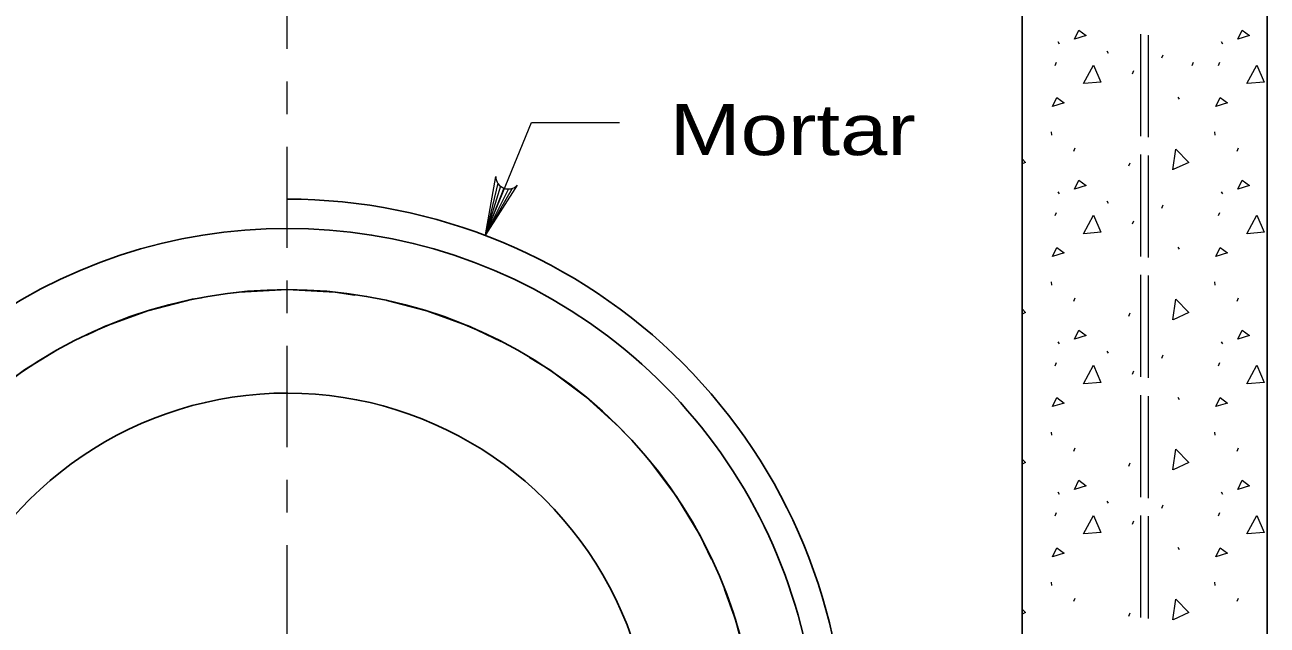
# Model space of a CAD drawing. Extents: x 1083.1 to 1117.1, y 719.4 to 763.4.
# Drawn here: x 1093.643 to 1097.446, y 731.113 to 732.95 of the extents above; entities that cross this region are included whole.
import ezdxf

# ---------------------------------------------------------------- set-up
doc = ezdxf.new("R2010")
doc.units = 0
doc.header["$LTSCALE"] = 0.062
doc.linetypes.add('DOT_DASHED', pattern=[7.7, 5, -1.2, 0.3, -1.2])
doc.linetypes.add('LONG_DASHED', pattern=[7.5, 6, -1.5])
doc.layers.add('1', color=7, linetype='Continuous', lineweight=13)

msp = doc.modelspace()

# ---------------------------------------------------------------- linework, layer by layer
at = {"layer": '1', "lineweight": 25}
msp.add_line((1096.69608, 730.80725), (1096.69608, 733.88517), dxfattribs=at)
at = {"layer": '1', "linetype": 'DOT_DASHED'}
msp.add_line((1094.44633, 731.04717), (1094.44633, 733.19283), dxfattribs=at)
at = {"layer": '1'}
for p, q in [((1096.80533, 732.89867), (1096.80983, 732.892)), ((1097.30533, 732.89867), (1097.30983, 732.892)), ((1096.95492, 732.8705), (1096.95933, 732.86383)), ((1097.12383, 732.84883), (1097.12825, 732.85875)), ((1096.797, 732.82558), (1096.80142, 732.83558)), ((1097.21667, 732.8255), (1097.22108, 732.8355)), ((1097.297, 732.82558), (1097.30142, 732.83558)), ((1097.03392, 732.80008), (1097.03833, 732.81008)), ((1097.17267, 732.72908), (1097.17708, 732.72242)), ((1095.05317, 732.30775), (1095.1945, 732.65108)), ((1095.1945, 732.65108), (1095.46383, 732.65108)), ((1096.78483, 732.62258), (1096.786, 732.61258)), ((1097.28483, 732.62258), (1097.286, 732.61258)), ((1096.85408, 732.56367), (1096.8585, 732.57367)), ((1097.35408, 732.56367), (1097.3585, 732.57367)), ((1097.02275, 732.51817), (1097.02725, 732.52817)), ((1095.09083, 732.46517), (1095.05317, 732.30775)), ((1095.09917, 732.456), (1095.05317, 732.30775)), ((1095.10908, 732.45033), (1095.05317, 732.30775)), ((1095.13542, 732.44967), (1095.05317, 732.30775)), ((1095.1235, 732.44775), (1095.05317, 732.30775)), ((1096.80533, 732.43933), (1096.80983, 732.43267)), ((1097.30533, 732.43933), (1097.30983, 732.43267)), ((1096.95492, 732.41108), (1096.95933, 732.40442)), ((1097.12383, 732.38942), (1097.12825, 732.39933)), ((1096.797, 732.36617), (1096.80142, 732.37617)), ((1097.297, 732.36617), (1097.30142, 732.37617)), ((1097.03392, 732.34075), (1097.03833, 732.35067)), ((1097.17267, 732.26975), (1097.17708, 732.26308)), ((1096.78483, 732.16325), (1096.786, 732.15325)), ((1097.28483, 732.16325), (1097.286, 732.15325)), ((1096.85408, 732.10433), (1096.8585, 732.11433)), ((1097.35408, 732.10433), (1097.3585, 732.11433)), ((1097.02275, 732.05883), (1097.02725, 732.06883)), ((1096.80533, 731.98), (1096.80983, 731.97333)), ((1097.30533, 731.98), (1097.30983, 731.97333)), ((1096.95492, 731.95175), (1096.95933, 731.94508)), ((1097.12383, 731.93008), (1097.12825, 731.94)), ((1096.797, 731.90683), (1096.80142, 731.91683)), ((1097.297, 731.90683), (1097.30142, 731.91683)), ((1097.03392, 731.88133), (1097.03833, 731.89133)), ((1097.17267, 731.81033), (1097.17708, 731.80367)), ((1096.78483, 731.70392), (1096.786, 731.69392)), ((1097.28483, 731.70392), (1097.286, 731.69392)), ((1096.85408, 731.645), (1096.8585, 731.655)), ((1097.35408, 731.645), (1097.3585, 731.655)), ((1097.02275, 731.5995), (1097.02725, 731.6095)), ((1096.80533, 731.52067), (1096.80983, 731.514)), ((1097.30533, 731.52067), (1097.30983, 731.514)), ((1096.95492, 731.49242), (1096.95933, 731.48575)), ((1096.797, 731.4475), (1096.80142, 731.4575)), ((1097.12383, 731.47075), (1097.12825, 731.48075)), ((1097.297, 731.4475), (1097.30142, 731.4575)), ((1097.03392, 731.422), (1097.03833, 731.432)), ((1097.17267, 731.351), (1097.17708, 731.34433)), ((1096.78483, 731.24458), (1096.786, 731.23458)), ((1097.28483, 731.24458), (1097.286, 731.23458)), ((1096.85408, 731.18567), (1096.8585, 731.19567)), ((1097.35408, 731.18567), (1097.3585, 731.19567)), ((1097.02275, 731.14017), (1097.02725, 731.15017))]:
    msp.add_line(p, q, dxfattribs=at)
at = {"layer": '1', "linetype": 'LONG_DASHED'}
for p, q in [((1097.05975, 732.60925), (1097.05975, 732.92167)), ((1097.08258, 732.6065), (1097.08258, 732.91892)), ((1097.05975, 732.241), (1097.05975, 732.55342)), ((1097.08258, 732.23825), (1097.08258, 732.55067)), ((1097.05975, 731.87267), (1097.05975, 732.18517)), ((1097.08258, 731.86992), (1097.08258, 732.18242)), ((1097.05975, 731.50442), (1097.05975, 731.81683)), ((1097.08258, 731.50167), (1097.08258, 731.81408)), ((1097.05975, 731.13617), (1097.05975, 731.44858)), ((1097.08258, 731.13342), (1097.08258, 731.44583))]:
    msp.add_line(p, q, dxfattribs=at)
at = {"layer": '1', "lineweight": 25}
msp.add_lwpolyline([(1097.44608, 733.17933), (1097.44608, 729.87108), (1097.44608, 727.90158)], dxfattribs=at)
at = {"layer": '1'}
for points in [[(1096.85625, 732.90642), (1096.86958, 732.93417), (1096.89183, 732.9175)], [(1097.35625, 732.90642), (1097.36958, 732.93417), (1097.39183, 732.9175)], [(1096.78917, 732.70017), (1096.8025, 732.72792), (1096.82475, 732.71125)], [(1097.28917, 732.70017), (1097.3025, 732.72792), (1097.32475, 732.71125)], [(1096.85625, 732.44708), (1096.86958, 732.47483), (1096.89183, 732.45817)], [(1097.35625, 732.44708), (1097.36958, 732.47483), (1097.39183, 732.45817)], [(1096.78917, 732.24083), (1096.8025, 732.26858), (1096.82475, 732.25192)], [(1097.28917, 732.24083), (1097.3025, 732.26858), (1097.32475, 732.25192)], [(1096.85625, 731.98775), (1096.86958, 732.0155), (1096.89183, 731.99883)], [(1097.35625, 731.98775), (1097.36958, 732.0155), (1097.39183, 731.99883)], [(1096.78917, 731.7815), (1096.8025, 731.80917), (1096.82475, 731.79258)], [(1097.28917, 731.7815), (1097.3025, 731.80917), (1097.32475, 731.79258)], [(1096.85625, 731.52842), (1096.86958, 731.55617), (1096.89183, 731.5395)], [(1097.35625, 731.52842), (1097.36958, 731.55617), (1097.39183, 731.5395)], [(1096.78917, 731.32208), (1096.8025, 731.34983), (1096.82475, 731.33325)], [(1097.28917, 731.32208), (1097.3025, 731.34983), (1097.32475, 731.33325)]]:
    msp.add_lwpolyline(points, close=True, dxfattribs=at)
for points in [[(1096.884, 732.77008), (1096.914, 732.82675), (1096.93733, 732.77458), (1096.88517, 732.77008)], [(1097.384, 732.77008), (1097.414, 732.82675), (1097.43733, 732.77458), (1097.38517, 732.77008)], [(1097.15783, 732.50667), (1097.16667, 732.57008), (1097.20642, 732.52908), (1097.15883, 732.507)], [(1096.69608, 732.53975), (1096.70642, 732.52908), (1096.69608, 732.52425)], [(1095.15075, 732.45958), (1095.05317, 732.30775), (1095.08483, 732.4855)], [(1096.884, 732.31083), (1096.914, 732.36733), (1096.93733, 732.31525), (1096.88517, 732.31083)], [(1097.384, 732.31083), (1097.414, 732.36733), (1097.43733, 732.31525), (1097.38517, 732.31083)], [(1097.15783, 732.04733), (1097.16667, 732.11075), (1097.20642, 732.06975), (1097.15883, 732.04767)], [(1096.69608, 732.08042), (1096.70642, 732.06975), (1096.69608, 732.06492)], [(1096.884, 731.85142), (1096.914, 731.908), (1096.93733, 731.85583), (1096.88517, 731.85142)], [(1097.384, 731.85142), (1097.414, 731.908), (1097.43733, 731.85583), (1097.38517, 731.85142)], [(1097.15783, 731.588), (1097.16667, 731.65142), (1097.20642, 731.61042), (1097.15883, 731.58842)], [(1096.69608, 731.62108), (1096.70642, 731.61042), (1096.69608, 731.60567)], [(1096.884, 731.39208), (1096.914, 731.44867), (1096.93733, 731.3965), (1096.88517, 731.39208)], [(1097.384, 731.39208), (1097.414, 731.44867), (1097.43733, 731.3965), (1097.38517, 731.39208)], [(1097.15783, 731.12867), (1097.16667, 731.19208), (1097.20642, 731.15108), (1097.15883, 731.12908)], [(1096.69608, 731.16175), (1096.70642, 731.15108), (1096.69608, 731.14633)]]:
    msp.add_lwpolyline(points, dxfattribs=at)
msp.add_arc((1095.123, 732.48588), 0.03822, 180.66621, 316.49234, dxfattribs=at)
at = {"layer": '1', "lineweight": 25}
for centre, major_axis, start_param, end_param in [((1094.44629, 730.70244), (-1.62494, 0), 2.7681167, 6.6566612), ((1094.44629, 730.70592), (1.71088, 0), 6.281164, 7.8539816), ((1094.44629, 730.70246), (1.43743, 0), 5.7812107, 9.9267526), ((1094.44633, 730.70595), (-1.1172, 0), 2.3192456, 7.102687)]:
    msp.add_ellipse(centre, major_axis=major_axis, ratio=0.999895, start_param=start_param, end_param=end_param, dxfattribs=at)
at = {"layer": '1', "linetype": 'LONG_DASHED', "lineweight": 25}
msp.add_ellipse((1094.44629, 730.70246), major_axis=(1.43743, 0), ratio=0.999895, dxfattribs=at)

# ---------------------------------------------------------------- texts
at = {"layer": '1', "width": 1.25}
msp.add_text('Mortar', height=0.156, dxfattribs=at).set_placement((1095.617, 732.55133))

doc.saveas('drawing.dxf')
